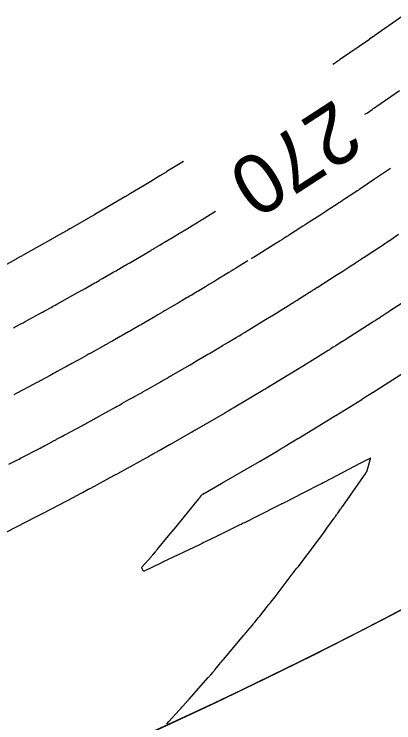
# Model space of a CAD drawing. Extents: x 1710723 to 1713003, y 548603 to 551142.
# Drawn here: x 1711935 to 1711973.4, y 549261.7 to 549333.3 of the extents above; entities that cross this region are included whole.
import ezdxf

# ---------------------------------------------------------------- set-up
doc = ezdxf.new("R2010")
doc.units = 0
for name, color, linetype in [('R_Contour Annot', 7, 'Continuous'), ('R_Contours', 7, 'Continuous'), ('R_Horz Alg', 7, 'Continuous'), ('R_Striping', 7, 'Continuous')]:
    doc.layers.add(name, color=color, linetype=linetype)

msp = doc.modelspace()

# ---------------------------------------------------------------- linework, layer by layer
at = {"layer": 'R_Contours'}
for points in [[(1711974.291, 549333.099), (1711971.511, 549331.131), (1711971.472, 549331.104), (1711971.433, 549331.076), (1711971.394, 549331.048), (1711971.354, 549331.021), (1711971.099, 549330.843), (1711970.97, 549330.752), (1711970.95, 549330.738), (1711967.94, 549328.657), (1711967.897, 549328.627), (1711967.854, 549328.597), (1711967.811, 549328.568), (1711967.768, 549328.538), (1711967.595, 549328.42), (1711967.551, 549328.39), (1711967.508, 549328.361), (1711967.465, 549328.332), (1711967.421, 549328.303), (1711967.244, 549328.184)], [(1711970.502, 549323.161), (1711970.506, 549323.163), (1711970.627, 549323.245), (1711970.747, 549323.328), (1711971.229, 549323.657), (1711971.349, 549323.739), (1711971.47, 549323.822), (1711971.59, 549323.905), (1711971.71, 549323.988), (1711973.991, 549325.565)], [(1711952.141, 549318.391), (1711950.473, 549317.365), (1711950.414, 549317.329), (1711950.355, 549317.293), (1711950.296, 549317.257), (1711950.237, 549317.221), (1711950.001, 549317.077), (1711949.942, 549317.041), (1711949.883, 549317.006), (1711949.824, 549316.97), (1711949.765, 549316.934), (1711948.854, 549316.383), (1711948.682, 549316.279), (1711948.51, 549316.176), (1711948.338, 549316.073), (1711948.166, 549315.97), (1711946.784, 549315.144), (1711946.71, 549315.1), (1711946.587, 549315.026), (1711946.562, 549315.011), (1711946.537, 549314.996), (1711946.512, 549314.982), (1711946.488, 549314.967), (1711946.346, 549314.883), (1711946.314, 549314.864), (1711946.282, 549314.846), (1711946.25, 549314.827), (1711946.218, 549314.808), (1711943.199, 549313.039), (1711943.145, 549313.007), (1711943.09, 549312.975), (1711943.036, 549312.944), (1711942.982, 549312.912), (1711942.765, 549312.786), (1711942.71, 549312.755), (1711942.656, 549312.723), (1711942.602, 549312.692), (1711942.547, 549312.661), (1711940.798, 549311.655), (1711940.764, 549311.636), (1711940.731, 549311.617), (1711940.698, 549311.598), (1711940.665, 549311.579), (1711940.498, 549311.485), (1711940.432, 549311.447), (1711940.399, 549311.428), (1711939.23, 549310.765), (1711939.185, 549310.739), (1711939.14, 549310.714), (1711939.051, 549310.664), (1711939.006, 549310.639), (1711938.962, 549310.614), (1711935.884, 549308.898), (1711935.829, 549308.867), (1711935.774, 549308.837), (1711935.719, 549308.806), (1711935.664, 549308.776), (1711935.443, 549308.654), (1711935.388, 549308.624), (1711935.333, 549308.593), (1711935.278, 549308.563), (1711935.223, 549308.533), (1711932.939, 549307.287)], [(1711973.085, 549317.685), (1711972.289, 549317.153), (1711972.087, 549317.017), (1711971.885, 549316.882), (1711971.682, 549316.746), (1711971.481, 549316.609), (1711969.988, 549315.601), (1711969.965, 549315.585), (1711969.941, 549315.569), (1711969.918, 549315.554), (1711969.894, 549315.538), (1711969.8, 549315.476), (1711969.776, 549315.46), (1711969.752, 549315.444), (1711969.729, 549315.429), (1711969.705, 549315.413), (1711969.587, 549315.334), (1711969.56, 549315.316), (1711969.532, 549315.298), (1711969.504, 549315.279), (1711969.477, 549315.261), (1711968.421, 549314.573), (1711968.235, 549314.452), (1711968.05, 549314.33), (1711967.866, 549314.209), (1711967.681, 549314.087), (1711966.776, 549313.491), (1711966.563, 549313.351), (1711966.351, 549313.211), (1711966.137, 549313.073), (1711965.924, 549312.935), (1711964.872, 549312.256), (1711964.659, 549312.119), (1711964.445, 549311.981), (1711964.232, 549311.845), (1711964.018, 549311.708), (1711962.866, 549310.973), (1711962.8, 549310.931), (1711962.735, 549310.889), (1711962.669, 549310.847), (1711962.603, 549310.806), (1711962.329, 549310.631), (1711962.269, 549310.593), (1711962.209, 549310.555), (1711962.149, 549310.517), (1711962.089, 549310.48), (1711961.849, 549310.329), (1711961.729, 549310.253), (1711961.609, 549310.178), (1711960.674, 549309.59), (1711960.516, 549309.491), (1711960.358, 549309.393), (1711960.2, 549309.294), (1711960.041, 549309.195), (1711959.408, 549308.802), (1711959.25, 549308.704), (1711959.091, 549308.606), (1711959.014, 549308.558)], [(1711934.984, 549301.583), (1711935.061, 549301.624), (1711935.138, 549301.666), (1711935.214, 549301.707), (1711935.72, 549301.98), (1711935.829, 549302.04), (1711935.939, 549302.099), (1711936.049, 549302.159), (1711936.158, 549302.218), (1711937.631, 549303.022), (1711937.774, 549303.099), (1711937.916, 549303.177), (1711938.059, 549303.256), (1711938.201, 549303.334), (1711938.769, 549303.648), (1711938.911, 549303.727), (1711939.053, 549303.805), (1711939.195, 549303.884), (1711939.337, 549303.963), (1711941.523, 549305.182), (1711941.58, 549305.214), (1711941.637, 549305.246), (1711941.693, 549305.277), (1711941.75, 549305.309), (1711941.977, 549305.437), (1711942.034, 549305.469), (1711942.09, 549305.501), (1711942.147, 549305.533), (1711942.203, 549305.565), (1711942.945, 549305.985), (1711943.029, 549306.033), (1711943.114, 549306.082), (1711943.199, 549306.13), (1711943.283, 549306.178), (1711943.622, 549306.371), (1711943.707, 549306.419), (1711943.791, 549306.467), (1711943.876, 549306.516), (1711943.961, 549306.564), (1711945.055, 549307.193), (1711945.194, 549307.273), (1711945.333, 549307.353), (1711945.472, 549307.433), (1711945.611, 549307.514), (1711946.166, 549307.836), (1711946.305, 549307.917), (1711946.444, 549307.998), (1711946.582, 549308.079), (1711946.721, 549308.16), (1711948.848, 549309.406), (1711948.927, 549309.452), (1711949.005, 549309.499), (1711949.084, 549309.545), (1711949.163, 549309.591), (1711949.512, 549309.798), (1711949.573, 549309.834), (1711949.634, 549309.87), (1711949.695, 549309.907), (1711949.756, 549309.943), (1711949.999, 549310.089), (1711950.06, 549310.125), (1711950.12, 549310.161), (1711950.181, 549310.198), (1711950.242, 549310.234), (1711951.272, 549310.849), (1711951.41, 549310.932), (1711951.549, 549311.015), (1711951.687, 549311.098), (1711951.825, 549311.182), (1711952.377, 549311.515), (1711952.515, 549311.599), (1711952.653, 549311.683), (1711952.791, 549311.766), (1711952.929, 549311.85), (1711953.493, 549312.194), (1711953.633, 549312.279), (1711953.773, 549312.364), (1711953.912, 549312.45), (1711954.052, 549312.536), (1711955.401, 549313.366)], [(1711934.508, 549287.784), (1711935.093, 549288.086), (1711935.239, 549288.162), (1711935.385, 549288.238), (1711935.53, 549288.314), (1711935.676, 549288.39), (1711937.658, 549289.431), (1711937.817, 549289.515), (1711937.976, 549289.599), (1711938.135, 549289.683), (1711938.293, 549289.767), (1711939.093, 549290.19), (1711939.169, 549290.231), (1711939.246, 549290.271), (1711939.322, 549290.312), (1711939.398, 549290.353), (1711939.781, 549290.557), (1711939.819, 549290.577), (1711939.856, 549290.597), (1711939.894, 549290.617), (1711939.931, 549290.637), (1711940.081, 549290.718), (1711940.156, 549290.758), (1711940.231, 549290.799), (1711941.866, 549291.683), (1711941.988, 549291.749), (1711942.11, 549291.815), (1711942.232, 549291.881), (1711942.354, 549291.947), (1711942.84, 549292.212), (1711942.962, 549292.279), (1711943.083, 549292.345), (1711943.205, 549292.412), (1711943.326, 549292.479), (1711945.29, 549293.564), (1711945.451, 549293.653), (1711945.612, 549293.743), (1711945.773, 549293.832), (1711945.934, 549293.921), (1711946.646, 549294.319), (1711946.772, 549294.389), (1711946.897, 549294.459), (1711947.023, 549294.529), (1711947.148, 549294.6), (1711947.772, 549294.951), (1711947.837, 549294.987), (1711947.901, 549295.023), (1711947.965, 549295.059), (1711948.028, 549295.095), (1711948.284, 549295.24), (1711948.348, 549295.277), (1711948.412, 549295.313), (1711948.476, 549295.349), (1711948.54, 549295.386), (1711949.718, 549296.056), (1711949.815, 549296.112), (1711949.912, 549296.167), (1711950.009, 549296.223), (1711950.106, 549296.278), (1711950.494, 549296.501), (1711950.59, 549296.557), (1711950.687, 549296.612), (1711950.784, 549296.668), (1711950.881, 549296.724), (1711952.825, 549297.853), (1711952.988, 549297.947), (1711953.151, 549298.042), (1711953.314, 549298.137), (1711953.476, 549298.233), (1711954.127, 549298.614), (1711954.29, 549298.709), (1711954.452, 549298.805), (1711954.615, 549298.901), (1711954.777, 549298.997), (1711955.561, 549299.46), (1711955.694, 549299.539), (1711955.828, 549299.618), (1711955.961, 549299.698), (1711956.094, 549299.777), (1711956.709, 549300.145), (1711956.8, 549300.2), (1711956.892, 549300.255), (1711956.984, 549300.31), (1711957.076, 549300.365), (1711957.484, 549300.608), (1711957.555, 549300.651), (1711957.626, 549300.693), (1711957.697, 549300.736), (1711957.768, 549300.779), (1711958.051, 549300.95), (1711958.122, 549300.993), (1711958.193, 549301.036), (1711958.264, 549301.079), (1711958.334, 549301.122), (1711960.283, 549302.309), (1711960.446, 549302.408), (1711960.608, 549302.507), (1711960.771, 549302.607), (1711960.933, 549302.707), (1711961.583, 549303.106), (1711961.745, 549303.206), (1711961.907, 549303.307), (1711962.069, 549303.407), (1711962.231, 549303.508), (1711963.401, 549304.234), (1711963.519, 549304.308), (1711963.637, 549304.381), (1711963.754, 549304.455), (1711963.872, 549304.529), (1711964.414, 549304.869), (1711964.497, 549304.921), (1711964.579, 549304.972), (1711964.661, 549305.024), (1711964.743, 549305.076), (1711965.144, 549305.328), (1711965.19, 549305.357), (1711965.235, 549305.385), (1711965.28, 549305.414), (1711965.325, 549305.442), (1711965.506, 549305.557), (1711965.551, 549305.586), (1711965.596, 549305.615), (1711965.641, 549305.644), (1711965.687, 549305.672), (1711967.607, 549306.898), (1711967.773, 549307.004), (1711967.938, 549307.11), (1711968.103, 549307.216), (1711968.268, 549307.322), (1711968.962, 549307.77), (1711969.11, 549307.866), (1711969.258, 549307.962), (1711969.406, 549308.058), (1711969.553, 549308.155), (1711970.141, 549308.543), (1711970.289, 549308.64), (1711970.436, 549308.737), (1711970.583, 549308.834), (1711970.731, 549308.93), (1711972.441, 549310.046), (1711972.46, 549310.058), (1711972.48, 549310.071), (1711972.499, 549310.084), (1711972.518, 549310.096), (1711972.595, 549310.148), (1711972.633, 549310.173), (1711972.672, 549310.199), (1711972.829, 549310.302), (1711972.862, 549310.324), (1711972.894, 549310.346), (1711972.927, 549310.367), (1711972.959, 549310.389), (1711973.911, 549311.032)], [(1711958.66, 549308.34), (1711957.631, 549307.707), (1711957.411, 549307.571), (1711957.19, 549307.436), (1711956.97, 549307.301), (1711956.749, 549307.166), (1711955.632, 549306.486), (1711955.527, 549306.423), (1711955.423, 549306.359), (1711955.319, 549306.296), (1711955.214, 549306.233), (1711954.796, 549305.98), (1711954.692, 549305.917), (1711954.587, 549305.854), (1711954.482, 549305.791), (1711954.378, 549305.729), (1711953.7, 549305.324), (1711953.603, 549305.266), (1711953.506, 549305.208), (1711953.409, 549305.15), (1711953.312, 549305.092), (1711952.925, 549304.86), (1711952.828, 549304.802), (1711952.731, 549304.744), (1711952.634, 549304.687), (1711952.537, 549304.629), (1711951.98, 549304.3), (1711951.854, 549304.226), (1711951.729, 549304.152), (1711951.603, 549304.078), (1711951.478, 549304.004), (1711950.243, 549303.281), (1711950.02, 549303.15), (1711949.797, 549303.02), (1711949.574, 549302.89), (1711949.351, 549302.76), (1711948.299, 549302.15), (1711948.155, 549302.066), (1711948.01, 549301.983), (1711947.865, 549301.899), (1711947.721, 549301.816), (1711947.123, 549301.473), (1711946.988, 549301.395), (1711946.852, 549301.317), (1711946.716, 549301.24), (1711946.58, 549301.162), (1711945.955, 549300.806), (1711945.859, 549300.752), (1711945.763, 549300.697), (1711945.667, 549300.643), (1711945.571, 549300.588), (1711945.177, 549300.365), (1711945.086, 549300.313), (1711944.995, 549300.262), (1711944.904, 549300.211), (1711944.813, 549300.159), (1711944.449, 549299.955), (1711944.358, 549299.903), (1711944.267, 549299.852), (1711944.176, 549299.801), (1711944.085, 549299.75), (1711942.79, 549299.029), (1711942.561, 549298.901), (1711942.333, 549298.774), (1711942.104, 549298.647), (1711941.875, 549298.521), (1711940.868, 549297.964), (1711940.684, 549297.863), (1711940.5, 549297.762), (1711940.315, 549297.661), (1711940.131, 549297.56), (1711939.378, 549297.149), (1711939.201, 549297.053), (1711939.025, 549296.957), (1711938.848, 549296.861), (1711938.671, 549296.765), (1711937.723, 549296.253), (1711937.666, 549296.222), (1711937.608, 549296.191), (1711937.551, 549296.161), (1711937.494, 549296.13), (1711937.262, 549296.005), (1711937.207, 549295.975), (1711937.152, 549295.946), (1711937.096, 549295.916), (1711937.041, 549295.886), (1711936.82, 549295.768), (1711936.765, 549295.739), (1711936.709, 549295.709), (1711936.654, 549295.68), (1711936.599, 549295.651), (1711935.239, 549294.93), (1711935.005, 549294.806)], [(1711975.406, 549304.83), (1711972.986, 549303.251), (1711972.904, 549303.198), (1711972.822, 549303.144), (1711972.74, 549303.09), (1711972.658, 549303.036), (1711972.33, 549302.82), (1711972.248, 549302.766), (1711972.166, 549302.712), (1711972.084, 549302.659), (1711972.001, 549302.606), (1711971.615, 549302.356), (1711971.523, 549302.297), (1711971.431, 549302.238), (1711971.339, 549302.179), (1711971.247, 549302.12), (1711968.507, 549300.372), (1711968.458, 549300.341), (1711968.409, 549300.309), (1711968.31, 549300.246), (1711968.285, 549300.231), (1711968.26, 549300.215), (1711968.236, 549300.199), (1711968.211, 549300.184), (1711967.556, 549299.772), (1711967.428, 549299.691), (1711967.3, 549299.611), (1711967.043, 549299.45), (1711966.979, 549299.41), (1711966.915, 549299.37), (1711966.851, 549299.33), (1711966.787, 549299.29), (1711964.897, 549298.115), (1711964.81, 549298.062), (1711964.723, 549298.008), (1711964.636, 549297.954), (1711964.549, 549297.9), (1711964.201, 549297.686), (1711964.113, 549297.632), (1711964.026, 549297.579), (1711963.939, 549297.525), (1711963.852, 549297.472), (1711961.037, 549295.758), (1711961, 549295.736), (1711960.963, 549295.713), (1711960.925, 549295.691), (1711960.888, 549295.668), (1711960.739, 549295.578), (1711960.701, 549295.555), (1711960.664, 549295.533), (1711960.627, 549295.51), (1711960.589, 549295.488), (1711960.375, 549295.36), (1711960.278, 549295.302), (1711960.181, 549295.244), (1711959.263, 549294.694), (1711959.094, 549294.593), (1711958.925, 549294.492), (1711958.755, 549294.392), (1711958.586, 549294.291), (1711957.344, 549293.557), (1711957.26, 549293.507), (1711957.176, 549293.458), (1711957.092, 549293.409), (1711957.008, 549293.359), (1711956.672, 549293.163), (1711956.588, 549293.113), (1711956.504, 549293.064), (1711956.42, 549293.015), (1711956.336, 549292.967), (1711953.462, 549291.298), (1711953.413, 549291.27), (1711953.364, 549291.242), (1711953.315, 549291.214), (1711953.266, 549291.186), (1711953.07, 549291.073), (1711953.021, 549291.045), (1711952.972, 549291.017), (1711952.923, 549290.989), (1711952.874, 549290.961), (1711951.125, 549289.965), (1711951.061, 549289.929), (1711950.997, 549289.893), (1711950.87, 549289.82), (1711950.838, 549289.802), (1711950.806, 549289.784), (1711950.774, 549289.766), (1711950.742, 549289.748), (1711949.686, 549289.155), (1711949.607, 549289.11), (1711949.528, 549289.066), (1711949.448, 549289.021), (1711949.369, 549288.977), (1711949.051, 549288.8), (1711948.971, 549288.755), (1711948.892, 549288.711), (1711948.812, 549288.667), (1711948.732, 549288.623), (1711945.784, 549286.994), (1711945.726, 549286.962), (1711945.667, 549286.929), (1711945.608, 549286.897), (1711945.549, 549286.865), (1711945.313, 549286.736), (1711945.255, 549286.704), (1711945.196, 549286.672), (1711945.137, 549286.64), (1711945.078, 549286.608), (1711942.739, 549285.345), (1711942.668, 549285.306), (1711942.579, 549285.258), (1711942.543, 549285.239), (1711942.525, 549285.229), (1711941.932, 549284.913), (1711941.857, 549284.873), (1711941.782, 549284.833), (1711941.707, 549284.793), (1711941.632, 549284.753), (1711941.331, 549284.594), (1711941.256, 549284.554), (1711941.181, 549284.515), (1711941.106, 549284.475), (1711941.031, 549284.435), (1711938.009, 549282.848), (1711937.941, 549282.813), (1711937.874, 549282.777), (1711937.806, 549282.742), (1711937.739, 549282.707), (1711937.469, 549282.568), (1711937.401, 549282.533), (1711937.333, 549282.498), (1711937.266, 549282.463), (1711937.198, 549282.429), (1711934.247, 549280.916)], [(1711950.457, 549261.55), (1711950.664, 549261.775), (1711951.725, 549262.926), (1711951.816, 549263.025), (1711951.907, 549263.124), (1711951.997, 549263.223), (1711952.087, 549263.323), (1711952.607, 549263.901), (1711952.625, 549263.922), (1711952.644, 549263.943), (1711952.719, 549264.027), (1711954.648, 549266.218), (1711954.706, 549266.284), (1711954.764, 549266.351), (1711954.823, 549266.418), (1711954.88, 549266.485), (1711955.111, 549266.753), (1711955.169, 549266.82), (1711955.226, 549266.887), (1711955.283, 549266.955), (1711955.34, 549267.023), (1711955.81, 549267.588), (1711955.907, 549267.704), (1711956.004, 549267.821), (1711956.102, 549267.937), (1711956.2, 549268.053), (1711958.269, 549270.499), (1711958.368, 549270.617), (1711958.467, 549270.735), (1711958.565, 549270.853), (1711958.664, 549270.972), (1711959.127, 549271.536), (1711959.189, 549271.611), (1711959.25, 549271.686), (1711959.311, 549271.762), (1711959.373, 549271.838), (1711959.616, 549272.14), (1711959.738, 549272.292), (1711959.86, 549272.443), (1711960.548, 549273.298), (1711960.657, 549273.434), (1711960.766, 549273.57), (1711960.874, 549273.706), (1711960.982, 549273.843), (1711961.413, 549274.39), (1711961.52, 549274.527), (1711961.627, 549274.665), (1711961.733, 549274.803), (1711961.839, 549274.941), (1711963.153, 549276.665), (1711963.307, 549276.867), (1711963.461, 549277.068), (1711963.616, 549277.269), (1711963.772, 549277.47), (1711964.57, 549278.499), (1711964.638, 549278.587), (1711964.706, 549278.675), (1711964.773, 549278.763), (1711964.84, 549278.852), (1711965.107, 549279.207), (1711965.173, 549279.296), (1711965.24, 549279.385), (1711965.306, 549279.474), (1711965.372, 549279.563), (1711966.13, 549280.596), (1711966.263, 549280.778), (1711966.396, 549280.961), (1711966.528, 549281.143), (1711966.66, 549281.326), (1711967.389, 549282.338), (1711967.419, 549282.381), (1711967.45, 549282.424), (1711967.482, 549282.467), (1711967.513, 549282.509), (1711967.638, 549282.679), (1711967.669, 549282.722), (1711967.7, 549282.765), (1711967.731, 549282.808), (1711967.762, 549282.851), (1711968.036, 549283.235), (1711968.092, 549283.314), (1711968.148, 549283.393), (1711968.203, 549283.471), (1711968.258, 549283.551), (1711970.581, 549286.893), (1711970.595, 549286.913), (1711970.609, 549286.933), (1711970.622, 549286.953), (1711970.636, 549286.973), (1711970.691, 549287.055), (1711970.703, 549287.075), (1711970.714, 549287.097), (1711970.723, 549287.119), (1711970.731, 549287.142), (1711970.958, 549287.983), (1711970.97, 549288.026), (1711970.982, 549288.07), (1711970.994, 549288.114), (1711971.005, 549288.158), (1711971.052, 549288.333), (1711971.057, 549288.369), (1711971.049, 549288.388), (1711971.029, 549288.391), (1711970.995, 549288.378), (1711970.124, 549287.916), (1711970.095, 549287.9), (1711970.065, 549287.885), (1711966.419, 549285.984), (1711966.264, 549285.903), (1711966.109, 549285.823), (1711965.954, 549285.742), (1711965.798, 549285.662), (1711964.482, 549284.986), (1711964.419, 549284.954), (1711964.355, 549284.921), (1711964.291, 549284.888), (1711964.227, 549284.856), (1711962.319, 549283.886), (1711962.213, 549283.832), (1711962.106, 549283.779), (1711962, 549283.725), (1711961.894, 549283.672), (1711959.582, 549282.516), (1711958.31, 549281.881), (1711958.198, 549281.825), (1711958.086, 549281.769), (1711957.974, 549281.714), (1711957.862, 549281.658), (1711955.777, 549280.634), (1711955.719, 549280.606), (1711955.662, 549280.578), (1711955.604, 549280.55), (1711955.546, 549280.522), (1711954.337, 549279.934), (1711954.193, 549279.864), (1711954.049, 549279.795), (1711953.905, 549279.725), (1711953.761, 549279.656), (1711950.047, 549277.879), (1711950.021, 549277.866), (1711949.996, 549277.854), (1711949.97, 549277.842), (1711949.944, 549277.83), (1711948.165, 549276.995), (1711948.139, 549276.987), (1711948.116, 549276.989), (1711948.096, 549277.002), (1711948.081, 549277.025), (1711948.018, 549277.16), (1711948, 549277.197), (1711947.983, 549277.234), (1711947.948, 549277.308), (1711947.942, 549277.326), (1711947.941, 549277.343), (1711947.946, 549277.36), (1711947.957, 549277.376), (1711948.907, 549278.479), (1711948.958, 549278.538), (1711949.009, 549278.597), (1711949.06, 549278.657), (1711949.111, 549278.716), (1711949.313, 549278.953), (1711949.364, 549279.012), (1711949.414, 549279.072), (1711949.465, 549279.132), (1711949.514, 549279.192), (1711950.632, 549280.54), (1711950.825, 549280.772), (1711951.017, 549281.004), (1711951.209, 549281.237), (1711951.401, 549281.47), (1711952.255, 549282.509), (1711952.402, 549282.689), (1711952.549, 549282.869), (1711952.695, 549283.05), (1711952.84, 549283.231), (1711953.692, 549284.298), (1711953.727, 549284.341), (1711953.761, 549284.384), (1711953.778, 549284.405), (1711953.796, 549284.427), (1711953.967, 549284.646), (1711954, 549284.684), (1711954.036, 549284.719), (1711954.076, 549284.75), (1711954.118, 549284.777), (1711956.031, 549285.865), (1711956.043, 549285.873), (1711959.848, 549288.08), (1711959.868, 549288.093), (1711959.91, 549288.117), (1711961.61, 549289.122), (1711961.816, 549289.244), (1711962.021, 549289.366), (1711962.227, 549289.489), (1711962.432, 549289.612), (1711963.659, 549290.346), (1711963.71, 549290.376), (1711963.74, 549290.395), (1711967.42, 549292.635), (1711967.456, 549292.657), (1711967.527, 549292.701), (1711967.563, 549292.723), (1711970.173, 549294.345), (1711970.204, 549294.365), (1711970.298, 549294.423), (1711971.278, 549295.04), (1711971.328, 549295.072), (1711974.886, 549297.342)]]:
    msp.add_lwpolyline(points, dxfattribs=at)
at = {"layer": 'R_Horz Alg'}
for centre, radius, start, end in [((1711727.021, 549745.305), 532.984, 270.64281, 347.20664), ((1711777.174, 549719.88), 636.62, 271.078651, 340.773399)]:
    msp.add_arc(centre, radius, start, end, dxfattribs=at)
at = {"layer": 'R_Striping'}
msp.add_arc((1711727.021, 549745.305), 532.984, 270.64281, 315.21532, dxfattribs=at)

# ---------------------------------------------------------------- texts
at = {"layer": 'R_Contour Annot'}
msp.add_text('270', height=6, rotation=212.9689, dxfattribs=at).set_placement((1711967.482, 549324.778))

doc.saveas('drawing.dxf')
